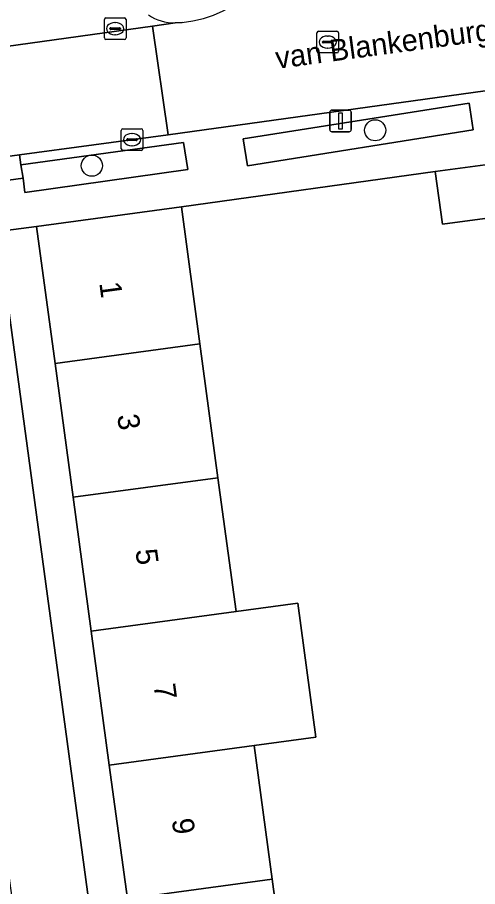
# Model space of a CAD drawing. Extents: x 159053 to 160042, y 380449 to 381423.
# Drawn here: x 159624.47 to 159645.73, y 380946 to 380986.2 of the extents above; entities that cross this region are included whole.
import ezdxf

# ---------------------------------------------------------------- set-up
doc = ezdxf.new("R2010")
doc.units = 0
for name, color, linetype in [('IMGEO_Boom', 7, 'Continuous'), ('IMGEO_Erf', 7, 'Continuous'), ('IMGEO_Groenvoorziening', 7, 'Continuous'), ('IMGEO_Kolk', 7, 'Continuous'), ('IMGEO_Lichtmast', 7, 'Continuous'), ('IMGEO_Muur', 7, 'Continuous'), ('IMGEO_Openbare_ruimte_label', 7, 'Continuous'), ('IMGEO_Pand', 7, 'Continuous'), ('IMGEO_Pand_nummerreeks', 7, 'Continuous'), ('IMGEO_Parkeervlak_open', 7, 'Continuous'), ('IMGEO_Rijbaan_lokaal_open', 7, 'Continuous'), ('IMGEO_Rioolput', 7, 'Continuous'), ('IMGEO_Voetpad_op_trap', 7, 'Continuous'), ('IMGEO_Voetpad_open', 7, 'Continuous')]:
    doc.layers.add(name, color=color, linetype=linetype)

msp = doc.modelspace()

# ---------------------------------------------------------------- linework, layer by layer
at = {"layer": 'IMGEO_Boom'}
for centre in [(159641.002, 380980.981), (159627.913, 380979.345)]:
    msp.add_circle(centre, 0.489, dxfattribs=at)
at = {"layer": 'IMGEO_Erf'}
msp.add_lwpolyline([(159648.031, 380977.168), (159644.108, 380976.638), (159643.779, 380979.075), (159632.047, 380977.442), (159632.902, 380971.105), (159633.738, 380964.913), (159634.574, 380958.722), (159637.428, 380959.108), (159638.265, 380952.918), (159635.41, 380952.532), (159636.245, 380946.341), (159637.081, 380940.15), (159640.444, 380940.605), (159641.302, 380934.262), (159637.937, 380933.808), (159631.246, 380932.905), (159631.447, 380931.413), (159631.692, 380931.446), (159632.229, 380927.466), (159678.267, 380933.693)], dxfattribs=at)
at = {"layer": 'IMGEO_Groenvoorziening'}
for points in [[(159645.535, 380980.996), (159645.338, 380982.24), (159634.901, 380980.587), (159635.098, 380979.343)], [(159632.151, 380980.416), (159624.635, 380979.384), (159624.733, 380978.767), (159624.82, 380978.099), (159632.343, 380979.164)]]:
    msp.add_lwpolyline(points, close=True, dxfattribs=at)
at = {"layer": 'IMGEO_Kolk'}
for p, q in [((159628.489, 380985.255), (159628.489, 380986.107)), ((159628.564, 380986.181), (159629.416, 380986.181)), ((159629.49, 380986.107), (159629.49, 380985.255)), ((159628.748, 380985.675), (159628.748, 380985.687)), ((159628.791, 380985.724), (159629.189, 380985.724)), ((159628.977, 380985.961), (159629.002, 380985.961)), ((159629.232, 380985.687), (159629.232, 380985.675)), ((159629.186, 380985.638), (159628.788, 380985.638)), ((159629, 380985.401), (159628.975, 380985.401)), ((159629.416, 380985.181), (159628.564, 380985.181)), ((159629.269, 380980.123), (159629.269, 380980.975)), ((159629.344, 380981.049), (159630.196, 380981.049)), ((159630.27, 380980.975), (159630.27, 380980.123)), ((159629.528, 380980.543), (159629.528, 380980.555)), ((159629.966, 380980.506), (159629.568, 380980.506)), ((159629.571, 380980.592), (159629.969, 380980.592)), ((159629.757, 380980.829), (159629.782, 380980.829)), ((159630.012, 380980.555), (159630.012, 380980.543)), ((159630.196, 380980.049), (159629.344, 380980.049)), ((159629.78, 380980.269), (159629.755, 380980.269))]:
    msp.add_line(p, q, dxfattribs=at)
for points in [[(159628.489, 380985.255), (159628.489, 380986.107)], [(159628.564, 380986.181), (159629.416, 380986.181)], [(159629.49, 380986.107), (159629.49, 380985.255)], [(159629.416, 380985.181), (159628.564, 380985.181)], [(159629.269, 380980.123), (159629.269, 380980.975)], [(159629.344, 380981.049), (159630.196, 380981.049)], [(159630.27, 380980.975), (159630.27, 380980.123)], [(159630.196, 380980.049), (159629.344, 380980.049)]]:
    msp.add_lwpolyline(points, dxfattribs=at)
for centre, radius, start, end in [((159628.566, 380986.105), 0.0765, 91.552, 178.448), ((159628.566, 380986.105), 0.0765, 91.552, 178.448), ((159629.414, 380986.105), 0.0765, 1.552, 88.448), ((159629.414, 380986.105), 0.0765, 1.552, 88.448), ((159628.788, 380985.684), 0.0403, 85.8775, 175.7526), ((159628.785, 380985.674), 0.0366, 178.938, 274.7102), ((159629.189, 380985.681), 0.043, 264.8664, 352.4533), ((159629.193, 380985.686), 0.0386, 1.7309, 96.639), ((159628.566, 380985.257), 0.0765, 181.552, 268.448), ((159628.566, 380985.257), 0.0765, 181.552, 268.448), ((159629.414, 380985.257), 0.0765, 271.552, 358.448), ((159629.414, 380985.257), 0.0765, 271.552, 358.448), ((159629.346, 380980.973), 0.0765, 91.552, 178.448), ((159629.346, 380980.973), 0.0765, 91.552, 178.448), ((159630.194, 380980.973), 0.0765, 1.552, 88.448), ((159630.194, 380980.973), 0.0765, 1.552, 88.448), ((159629.568, 380980.552), 0.0403, 85.8775, 175.7526), ((159629.565, 380980.542), 0.0366, 178.938, 274.7102), ((159629.969, 380980.549), 0.043, 264.8664, 352.4533), ((159629.973, 380980.554), 0.0386, 1.7309, 96.639), ((159629.346, 380980.125), 0.0765, 181.552, 268.448), ((159629.346, 380980.125), 0.0765, 181.552, 268.448), ((159630.194, 380980.125), 0.0765, 271.552, 358.448), ((159630.194, 380980.125), 0.0765, 271.552, 358.448)]:
    msp.add_arc(centre, radius, start, end, dxfattribs=at)
for centre, major_axis, ratio, start_param, end_param in [((159628.976, 380985.681), (-0.387, 0.002), 0.722429, 4.712389, 7.853982), ((159629.001, 380985.681), (-0.39, 0.002), 0.717154, 1.570796, 4.712389), ((159629.756, 380980.549), (-0.387, 0.002), 0.722429, 4.712389, 7.853982), ((159629.781, 380980.549), (-0.39, 0.002), 0.717154, 1.570796, 4.712389)]:
    msp.add_ellipse(centre, major_axis=major_axis, ratio=ratio, start_param=start_param, end_param=end_param, dxfattribs=at)
at = {"layer": 'IMGEO_Lichtmast'}
for p, q in [((159638.906, 380981.015), (159638.906, 380981.815)), ((159638.906, 380981.815), (159638.906, 380981.015)), ((159639.006, 380981.915), (159639.796, 380981.915)), ((159639.796, 380981.915), (159639.006, 380981.915)), ((159639.896, 380981.815), (159639.896, 380981.015)), ((159639.896, 380981.015), (159639.896, 380981.815)), ((159639.796, 380980.915), (159639.006, 380980.915)), ((159639.006, 380980.915), (159639.796, 380980.915))]:
    msp.add_line(p, q, dxfattribs=at)
msp.add_lwpolyline([(159639.326, 380981.79), (159639.476, 380981.79), (159639.476, 380981.04), (159639.326, 380981.04), (159639.326, 380981.79)], dxfattribs=at)
for centre, start, end in [((159639.006, 380981.815), 90, 180), ((159639.006, 380981.815), 90, 180), ((159639.796, 380981.815), 0, 90), ((159639.796, 380981.815), 360, 90), ((159639.006, 380981.015), 180, 270), ((159639.006, 380981.015), 180, 270), ((159639.796, 380981.015), 270, 0), ((159639.796, 380981.015), 270, 0)]:
    msp.add_arc(centre, 0.1, start, end, dxfattribs=at)
at = {"layer": 'IMGEO_Muur'}
msp.add_lwpolyline([(159632.047, 380977.442), (159643.779, 380979.075)], dxfattribs=at)
at = {"layer": 'IMGEO_Pand'}
for points in [[(159648.031, 380977.168), (159647.702, 380979.605), (159643.779, 380979.075), (159644.108, 380976.638)], [(159632.902, 380971.105), (159632.047, 380977.442), (159625.356, 380976.539), (159626.212, 380970.2)], [(159632.902, 380971.105), (159626.212, 380970.2), (159627.048, 380964.008), (159633.738, 380964.913)], [(159634.574, 380958.722), (159633.738, 380964.913), (159627.048, 380964.008), (159627.883, 380957.817)], [(159628.719, 380951.627), (159635.41, 380952.532), (159638.265, 380952.918), (159637.428, 380959.108), (159634.574, 380958.722), (159627.883, 380957.817)], [(159629.554, 380945.436), (159636.245, 380946.341), (159635.41, 380952.532), (159628.719, 380951.627)], [(159630.39, 380939.245), (159637.081, 380940.15), (159636.245, 380946.341), (159629.554, 380945.436)]]:
    msp.add_lwpolyline(points, close=True, dxfattribs=at)
at = {"layer": 'IMGEO_Parkeervlak_open'}
msp.add_lwpolyline([(159591.927, 380980.432), (159592.902, 380980.536), (159630.712, 380985.796), (159631.757, 380985.948)], dxfattribs=at)
msp.add_arc((159631.707, 380987.945), 1.998, 234.0964, 271.4413, dxfattribs=at)
at = {"layer": 'IMGEO_Rijbaan_lokaal_open'}
for points in [[(159632.08, 380985.974), (159631.757, 380985.948), (159630.712, 380985.796), (159631.442, 380980.776), (159648.745, 380983.173), (159648.044, 380988.138), (159647.992, 380988.506)], [(159609.343, 380940.538), (159608.889, 380943.948), (159606.546, 380961.427), (159604.872, 380973.622), (159601.418, 380973.158), (159607.475, 380928.135), (159612.528, 380928.819), (159613.067, 380924.84), (159625.388, 380926.542), (159624.851, 380930.523), (159629.685, 380931.175), (159623.567, 380976.306), (159620.023, 380975.823), (159621.831, 380963.292), (159624.158, 380945.926), (159624.601, 380942.698)]]:
    msp.add_lwpolyline(points, dxfattribs=at)
msp.add_lwpolyline([(159631.442, 380980.776), (159630.712, 380985.796), (159592.902, 380980.536), (159593.547, 380975.614), (159599.594, 380976.425), (159606.648, 380977.395), (159616.632, 380978.772), (159624.562, 380979.841)], close=True, dxfattribs=at)
msp.add_arc((159631.653, 380991.171), 5.215, 274.7006, 0.7228, dxfattribs=at)
at = {"layer": 'IMGEO_Rioolput'}
for p, q in [((159638.311, 380984.636), (159638.311, 380985.488)), ((159638.386, 380985.562), (159639.238, 380985.562)), ((159638.799, 380985.342), (159638.824, 380985.342)), ((159639.312, 380985.488), (159639.312, 380984.636)), ((159638.57, 380985.056), (159638.57, 380985.068)), ((159639.008, 380985.019), (159638.61, 380985.019)), ((159638.613, 380985.105), (159639.011, 380985.105)), ((159639.054, 380985.068), (159639.054, 380985.056)), ((159639.238, 380984.562), (159638.386, 380984.562)), ((159638.822, 380984.782), (159638.797, 380984.782))]:
    msp.add_line(p, q, dxfattribs=at)
for points in [[(159638.311, 380984.636), (159638.311, 380985.488)], [(159638.386, 380985.562), (159639.238, 380985.562)], [(159639.312, 380985.488), (159639.312, 380984.636)], [(159639.238, 380984.562), (159638.386, 380984.562)]]:
    msp.add_lwpolyline(points, dxfattribs=at)
for centre, radius, start, end in [((159638.388, 380985.486), 0.0765, 91.552, 178.448), ((159638.388, 380985.486), 0.0765, 91.552, 178.448), ((159639.236, 380985.486), 0.0765, 1.552, 88.448), ((159639.236, 380985.486), 0.0765, 1.552, 88.448), ((159638.61, 380985.065), 0.0403, 85.8775, 175.7526), ((159638.607, 380985.055), 0.0366, 178.938, 274.7102), ((159639.011, 380985.062), 0.043, 264.8664, 352.4533), ((159639.015, 380985.067), 0.0386, 1.7309, 96.639), ((159638.388, 380984.638), 0.0765, 181.552, 268.448), ((159638.388, 380984.638), 0.0765, 181.552, 268.448), ((159639.236, 380984.638), 0.0765, 271.552, 358.448), ((159639.236, 380984.638), 0.0765, 271.552, 358.448)]:
    msp.add_arc(centre, radius, start, end, dxfattribs=at)
for centre, major_axis, ratio, start_param, end_param in [((159638.798, 380985.062), (-0.387, 0.002), 0.722429, 4.712389, 7.853982), ((159638.823, 380985.062), (-0.39, 0.002), 0.717154, 1.570796, 4.712389)]:
    msp.add_ellipse(centre, major_axis=major_axis, ratio=ratio, start_param=start_param, end_param=end_param, dxfattribs=at)
at = {"layer": 'IMGEO_Voetpad_op_trap'}
for points in [[(159631.757, 380985.948), (159632.08, 380985.974)], [(159632.047, 380977.442), (159643.779, 380979.075), (159647.702, 380979.605), (159649.167, 380979.794), (159653.334, 380980.357), (159664.907, 380981.903), (159671.666, 380982.815), (159672.495, 380982.592), (159676.976, 380983.199), (159680.088, 380984.138), (159688.89, 380985.283), (159691.36, 380985.638)], [(159648.745, 380983.173), (159631.442, 380980.776), (159624.562, 380979.841), (159624.635, 380979.384), (159632.151, 380980.416), (159632.343, 380979.164), (159624.82, 380978.099), (159624.733, 380978.767), (159616.793, 380977.691), (159616.854, 380977.123), (159606.851, 380975.797), (159606.771, 380976.277), (159599.734, 380975.322), (159599.839, 380974.688), (159592.769, 380973.729), (159592.581, 380975.042), (159599.649, 380975.991), (159599.594, 380976.425), (159593.547, 380975.614), (159573.94, 380972.918)], [(159607.873, 380974.185), (159617.199, 380975.434), (159620.023, 380975.823), (159623.567, 380976.306), (159625.356, 380976.539), (159632.047, 380977.442)]]:
    msp.add_lwpolyline(points, dxfattribs=at)
for points in [[(159634.901, 380980.587), (159645.338, 380982.24), (159645.535, 380980.996), (159635.098, 380979.343)], [(159624.733, 380978.767), (159624.635, 380979.384), (159624.562, 380979.841), (159616.632, 380978.772), (159616.701, 380978.31), (159616.793, 380977.691)]]:
    msp.add_lwpolyline(points, close=True, dxfattribs=at)
for centre, radius, start, end in [((159631.653, 380991.171), 5.215, 274.7006, 0.7228), ((159631.707, 380987.945), 1.998, 234.0964, 271.4413)]:
    msp.add_arc(centre, radius, start, end, dxfattribs=at)
at = {"layer": 'IMGEO_Voetpad_open'}
msp.add_lwpolyline([(159628.719, 380951.627), (159627.883, 380957.817), (159627.048, 380964.008), (159626.212, 380970.2), (159625.356, 380976.539), (159623.567, 380976.306), (159629.685, 380931.175), (159631.447, 380931.413), (159631.246, 380932.905), (159630.39, 380939.245), (159629.554, 380945.436)], close=True, dxfattribs=at)

# ---------------------------------------------------------------- texts
at = {"layer": 'IMGEO_Openbare_ruimte_label'}
msp.add_text('van Blankenburgstraat', height=1, rotation=7.6439, dxfattribs=at).set_placement((159636.464, 380983.821))
at = {"layer": 'IMGEO_Pand_nummerreeks'}
for s, p in [('1', (159628.253, 380973.919)), ('3', (159629.079, 380967.799)), ('5', (159629.921, 380961.565)), ('7', (159630.762, 380955.332)), ('9', (159631.603, 380949.099))]:
    msp.add_text(s, height=1, rotation=277.6877, dxfattribs=at).set_placement(p)

doc.saveas('drawing.dxf')
